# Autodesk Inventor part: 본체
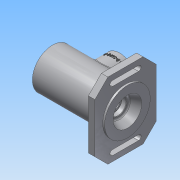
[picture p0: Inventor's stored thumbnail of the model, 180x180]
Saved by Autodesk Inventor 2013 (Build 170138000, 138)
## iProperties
Created: 2017-10
Part Number: 본체
Material: 알루미늄 6061
Document SubType Name: Modeling
Designer: Administrator
Density: 2.71 g/cm^3
Mass: 738.446 g
Surface Area: 652.229 cm^2
Volume: 272.489 cm^3
Author: Administrator
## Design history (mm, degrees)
sketch "스케치1"
  geometry: L1 (-56, 0)-(59, 0); L2 (-56, 0)-(-56, 21); L3 (-56, 31)-(59, 31); L4 (59, 31)-(59, 22); L5 (-56, 21)-(-47, 21); L6 (-47, 21)-(-47, 24); L7 (-47, 24)-(-44, 24); L8 (-44, 24)-(-44, 20); L9 (-31.75, 17.5)-(-31.75, 18.5); L10 (-31.75, 18.5)-(-30, 18.5); L11 (-30, 18.5)-(-30, 17.5); L12 (-30, 17.5)-(-19, 17.5); L13 (-19, 17.5)-(-19, 26); L14 (-19, 26)-(19, 26); L15 (19, 26)-(19, 17.5); L16 (19, 17.5)-(30, 17.5); L17 (30, 17.5)-(30, 16.5); L18 (30, 16.5)-(35, 16.5); L19 (35, 16.5)-(35, 10); L20 (35, 10)-(37.7, 10); L21 (37.7, 10)-(37.7, 12.5); L22 (37.7, 12.5)-(45, 12.5); L23 (45, 12.5)-(45, 16); L24 (45, 16)-(59, 22); L25 (-44, 20)-(-35, 20); L26 (-35, 20)-(-35, 17.5); L27 (-35, 17.5)-(-31.75, 17.5); L28 (59, 22)-(59, 0); L29 (-56, 21)-(-56, 31); 1 further point
  constraints: 58 end point, 17 parallel, 12 perpendicular, 2 collinear, 1 horizontal, 1 point on line
  dimensions: "d0" = 56 distance of L1.start point (0, 0); "d1" = 115 distance of L1.start L1.end; "d2" = 62 diameter of L3 L1; "d3" = 44 diameter of L4.end L1; "d4" = 32 diameter of L23.end L1; "d5" = 25 diameter of L22 L1; "d6" = 20 diameter of L20 L1; "d7" = 33 diameter of L18 L1; "d8" = 48 diameter of L7 L1; "d9" = 37 diameter of L10 L1; "d11" = 52 diameter of L14 L1; "d12" = 11 distance of L15.end L16.end; "d13" = 14 distance between parallel lines of L4 L23; "d14" = 7.3 distance of L21.end L22.end; "d15" = 2.7 distance between parallel lines of L19 L21; "d16" = 5 distance of L17.end L18.end; "d17" = 11 distance of L11.end L12.end; "d18" = 1.75 distance of L9.end L10.end; "d19" = 12 distance between parallel lines of L2 L8; "d20" = 40 diameter of L25 L1; "d21" = 21 distance between parallel lines of L2 L26; "d22" = 3 distance between parallel lines of L6 L8; "d23" = 42 diameter of L5 L1; "d24" = 35 diameter of L12 L1; "d25" = 26 distance from line of L2 L11.end
revolve "회전1" sketch "스케치1" stored, may be unused: angle "d26" = 90 deg
sketch "스케치2"
  geometry: C1 r 31 at (0, 0) reference; C2 r 35 at (0, 0)
  constraints: 1 centre point, 1 coincident
  dimensions: "d27" = 70 diameter of C2
extrude "돌출1" join sketch "스케치2" distance "d29" = 3; taper "d30" = 0 deg
sketch "스케치4"
  geometry: L1 (58, -47)-(-58, -47); L2 (-58, -47)-(-58, 47); L3 (-58, 47)-(58, 47); L4 (58, 47)-(58, -47); L5 (58, -47)-(-58, 47); L6 (-58, -47)-(58, 47); C1 r 31 at (0, 0) reference; C2 r 31 at (0, 0) reference
  constraints: 12 end point, 2 midpoint, 2 parallel, 1 horizontal, 1 perpendicular
  dimensions: "d36" = 116 distance between parallel lines of L4 L2; "d38" = 94 distance between parallel lines of L1 L3
extrude "돌출3" join sketch "스케치4" distance "d39" = 10; taper "d40" = 0 deg
sketch "스케치5"
  geometry: L1 (-58, 47)-(-58, -47) reference; L2 (-50, -20)-(-50, 20); L3 (-42, 20)-(-42, -20); C1 r 31 at (0, 0) reference; A1 r 4 centre (-46, 20) between (-42, 20) and (-50, 20); A2 r 4 centre (-46, -20) between (-50, -20) and (-42, -20)
  constraints: 4 end point, 4 point on circle, 4 tangent, 2 centre point, 2 parallel
  dimensions: "d41" = 20 vertical distance of A1.centre C1.centre; "d42" = 40 distance of A2.centre A1.centre; "d43" = 46 horizontal distance of C1.centre A2.centre; "d44" = 4 radius of A1
extrude "돌출4" cut sketch "스케치5" distance "d45" = 10; taper "d46" = 0 deg
chamfer "모따기1" distance "d47" = 20; stored, may be unused: second distance "d48" = 2, angle "d49" = 45 deg
node "작업 평면1"
sketch "스케치6"
  geometry: C1 r 25 at (0, 0); 1 further point
  constraints: 1 centre point, 1 coincident
  dimensions: "d51" = 50 diameter of C1
extrude "돌출5" join sketch "스케치6" stored distance "d53" = 10; taper "d54" = 0 deg
hole "구멍1" diameter "d57" = 32; stored, may be unused: countersink angle "d61" = 90 deg, drill point angle "d63" = 118 deg; dims "d55" = 10, "d56" = 10, "d58" = 6, "d59" = 4, "d60" = 2, "d62" = 8
fillet "모깎기1" dims "d64" = 3
fillet "모깎기2" dims "d65" = 0.3
chamfer "모따기2" distance "d66" = 0.7; stored, may be unused: second distance "d67" = 2, angle "d68" = 30 deg
node "작업 평면2"
sketch "스케치8"
  geometry: L1 (-25, 0)-(25, 0) reference; L2 (-56, -78)-(-56, -16) reference; 2 further points
  constraints: 1 other
  dimensions: "d70" = 10 vertical distance of point (0, -10) L1.end; "d71" = 56 distance from line of L2 point (0, -10)
feature "엠보싱1" sketch "스케치8" dims "d12" = 11, "d72" = 0.5, "d73" = 0
feature "스레드1" dims "d74" = 10, "d75" = 0
sketch "스케치9"
  geometry: C1 r 16 at (0, 0) reference; 1 further point
  constraints: 1 vertical alignment
  dimensions: "d76" = 20.5 distance of C1.centre point (0, 20.5)
hole "구멍2" sketch "스케치9" at (0, 20.5) diameter "d77" = 2.459; stored, may be unused: countersink angle "d81" = 90 deg, drill point angle "d83" = 118 deg; dims "d78" = 6, "d79" = 4, "d80" = 2, "d82" = 8
chamfer "모따기3" distance "d84" = 1; stored, may be unused: second distance "d85" = 2, angle "d86" = 30 deg
chamfer "모따기4" distance "d87" = 1; stored, may be unused: second distance "d88" = 2, angle "d89" = 30 deg
node "솔리드1"
mirror "대칭1"
mirror "대칭2"
other parameters: "d50" = 47
